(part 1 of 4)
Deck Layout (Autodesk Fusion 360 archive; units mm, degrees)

design "Deck Layout" references "Pinball Flipper Full bushing"
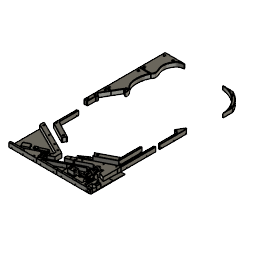
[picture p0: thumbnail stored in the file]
parameter "d345" = 2.4
sketch "Deck" plane through (0, 0, 0) normal (0, 0, 1) x axis (1, 0, 0)
  line L1 (500, 0) -> (0, 0)
  line L2 (500, 900) -> (500, 0)
  line L3 (0, 900) -> (500, 900)
  line L4 (0, 0) -> (0, 900)
  line L5 (250, 900) -> (250, 0)
  line L6 (265, 900) -> (265, 0)
  line L7 (235, 900) -> (235, 0)
  line L8 (475, 900) -> (475, 0)
  line L9 (25, 900) -> (25, 0)
  line L10 (500, 205) -> (0, 205)
  line L11 (500, 175) -> (0, 175)
  line L12 (175, 0) -> (175, 900)
  line L13 (325, 900) -> (325, 0)
  line L14 (187.7232, 167.6543) -> (175, 175)
  line L15 (189.6915, 175) -> (175, 175)
  line L16 (317.6007, 170.728) -> (325, 175)
  line L17 (333.544, 175) -> (325, 175)
  line L18 (317, 900) -> (317, 0)
  line L19 (183, 0) -> (183, 900)
  line L20 (500, 100) -> (0, 100)
  line L21 (500, 750) -> (500, 900)
  line L22 (500, 818.9103) -> (500, 750)
  line L23 (418.7386, 900) -> (350, 900)
  line L24 (0, 810) -> (500, 810)
  line L25 (0, 760) -> (500, 760)
  arc A1 centre (350, 750) radius 150 clockwise from (350, 900) to (500, 750)
  arc A2 centre (350, 750) radius 165 clockwise from (418.7386, 900) to (500, 818.7386)
  circle C1 centre (416.5624, 892.7435) radius 5
  circle C2 centre (416.5624, 892.7435) radius 2
  circle C3 centre (416.5624, 892.7435) radius 2
  circle C4 centre (416.5624, 892.7435) radius 5
  circle C5 centre (492.7435, 816.5624) radius 5
  circle C6 centre (492.7435, 816.5624) radius 2
  point P1 (0, 0)
  point P2 (0, 0)
  point P6 (0, 0)
  point P7 (250, 0)
  point P8 (250, 900)
  point P25 (175, 175)
  point P28 (325, 175)
  point P40 (350, 900)
  point P38 (350, 750)
  point P41 (350, 750)
  point P42 (500, 818.9103)
  point P43 (500, 818.7386)
  point P44 (418.7386, 900)
  coincident P1 P2
  horizontal L1
  perpendicular L1 L2
  perpendicular L2 L3
  coincident P1 P6
  perpendicular L1 L4
  midpoint L1 P7
  midpoint L3 P8
  horizontal L10
  horizontal L11
  horizontal L15
  coincident L11 P25
  coincident L12 P25
  horizontal L17
  coincident L11 P28
  coincident L13 P28
  horizontal L20
  perpendicular L3 L21
  coincident L3 P40
  coincident P38 P41
  coincident L21 P42
  coincident L2 P43
  coincident L3 P44
  tangent A1 L23
  concentric C1 C2
  concentric C3 C4
  concentric C5 C6
  dimension "d4" angle L14 L15 = 30
  dimension "d5" angle L16 L17 = 150
extrude "Extrude1" new body sketch "Deck" profile of L1 L2 L3 L4 L5 L6 L7 L8 L9 L10 L11 L12 L13 against normal blind 9
external_derived "ExternalDerived1"
move "Move1"
move "Move2"
move "Move3"
sketch "SCRATCH Sketch2" plane through (0, 0, 0) normal (0, 0, 1) x axis (1, 0, 0)
  line L1 (170.3253, 163.25) -> (183.8331, 184.2525)
  line L2 (165.6625, 180.1712) -> (177.0792, 173.7512)
  arc A1 centre (176.5753, 174.0753) radius 12.5 clockwise from (170.3253, 163.25) to (183.6642, 184.3709)
  point P2 (183.8331, 184.2525)
  point P4 (183.8331, 184.2525)
  point P3 (170.3253, 163.25)
  point P5 (170.3253, 163.25)
  point P9 (177.0792, 173.7512)
  point P10 (165.6625, 180.1712)
  coincident P2 P4
  coincident P3 P5
  midpoint L1 P9
  coincident A1 P10
move "Move4"
copy_paste_bodies "CopyPasteBodies1"
move "Move5"
move "Move6"
sketch "SCRATCH Sketch3" plane through (0, 0, 25.4) normal (0, 0, 1) x axis (-1, 0, 0)
  line L1 (-298.3283, -100.9362) -> (-297.8341, -101.7922)
  line L2 (-297.584, -100.5065) -> (-298.3283, -100.9362)
  line L3 (-297.0898, -101.3625) -> (-297.584, -100.5065)
  line L4 (-297.8341, -101.7922) -> (-297.0898, -101.3625)
  line L5 (-303.1949, -96.8044) -> (-299.6949, -102.8666)
  line L6 (-302.4506, -96.3746) -> (-303.1949, -96.8044)
  line L7 (-298.9506, -102.4368) -> (-302.4506, -96.3746)
  line L8 (-299.6949, -102.8666) -> (-298.9506, -102.4368)
  line L9 (-305.0971, -97.9026) -> (-302.5616, -102.2942)
  line L10 (-304.3528, -97.4729) -> (-305.0971, -97.9026)
  line L11 (-301.8173, -101.8644) -> (-304.3528, -97.4729)
  line L12 (-302.5616, -102.2942) -> (-301.8173, -101.8644)
  line L13 (-336.6609, -113.8819) -> (-335.4266, -116.0198)
  line L14 (-335.9166, -113.4522) -> (-336.6609, -113.8819)
  line L15 (-332.4094, -119.5268) -> (-335.9166, -113.4522)
  line L16 (-333.0876, -119.9183) -> (-332.4094, -119.5268)
  line L17 (-333.417, -119.3477) -> (-333.0876, -119.9183)
  curve K1 (-333.6687, -120.1628) -> (-333.417, -119.3477)
  curve K2 (-334.3039, -120.7529) -> (-333.6687, -120.1628)
  curve K3 (-335.4635, -121.0364) -> (-334.3039, -120.7529)
  curve K4 (-336.5842, -120.5946) -> (-335.4635, -121.0364)
  curve K5 (-337.4707, -119.5653) -> (-336.5842, -120.5946)
  curve K6 (-337.9295, -118.212) -> (-337.4707, -119.5653)
  curve K7 (-337.704, -116.9791) -> (-337.9295, -118.212)
  curve K8 (-336.9002, -116.1318) -> (-337.704, -116.9791)
  curve K9 (-336.1417, -115.9034) -> (-336.9002, -116.1318)
  curve K10 (-335.4266, -116.0198) -> (-336.1417, -115.9034)
  line L18 (-315.9189, -104.1506) -> (-314.5342, -106.549)
  line L19 (-315.1746, -103.7208) -> (-315.9189, -104.1506)
  line L20 (-312.6391, -108.1124) -> (-315.1746, -103.7208)
  line L21 (-313.309, -108.4992) -> (-312.6391, -108.1124)
  line L22 (-313.6695, -107.8747) -> (-313.309, -108.4992)
  curve K11 (-314.6494, -109.4054) -> (-313.6695, -107.8747)
  curve K12 (-315.4616, -109.6841) -> (-314.6494, -109.4054)
  curve K13 (-316.176, -109.5975) -> (-315.4616, -109.6841)
  curve K14 (-316.7251, -109.1812) -> (-316.176, -109.5975)
  curve K15 (-317.1842, -108.4815) -> (-316.7251, -109.1812)
  line L23 (-318.7432, -105.7812) -> (-317.1842, -108.4815)
  line L24 (-317.9989, -105.3514) -> (-318.7432, -105.7812)
  line L25 (-316.4566, -108.0228) -> (-317.9989, -105.3514)
  curve K16 (-315.977, -108.6529) -> (-316.4566, -108.0228)
  curve K17 (-315.4612, -108.8348) -> (-315.977, -108.6529)
  curve K18 (-314.8647, -108.6695) -> (-315.4612, -108.8348)
  curve K19 (-314.2181, -107.8938) -> (-314.8647, -108.6695)
  curve K20 (-314.5342, -106.549) -> (-314.2181, -107.8938)
  line L26 (-329.0977, -111.7594) -> (-327.7106, -114.1619)
  line L27 (-328.3534, -111.3296) -> (-329.0977, -111.7594)
  line L28 (-324.8534, -117.3918) -> (-328.3534, -111.3296)
  line L29 (-325.5977, -117.8215) -> (-324.8534, -117.3918)
  line L30 (-326.8535, -115.6464) -> (-325.5977, -117.8215)
  curve K21 (-327.8199, -117.0094) -> (-326.8535, -115.6464)
  curve K22 (-328.7787, -117.3065) -> (-327.8199, -117.0094)
  curve K23 (-329.6003, -117.0724) -> (-328.7787, -117.3065)
  curve K24 (-330.3236, -116.1777) -> (-329.6003, -117.0724)
  line L31 (-331.9303, -113.3948) -> (-330.3236, -116.1777)
  line L32 (-331.186, -112.965) -> (-331.9303, -113.3948)
  line L33 (-329.5792, -115.748) -> (-331.186, -112.965)
  curve K25 (-328.8682, -116.4209) -> (-329.5792, -115.748)
  curve K26 (-328.037, -116.2801) -> (-328.8682, -116.4209)
  curve K27 (-327.5137, -115.7492) -> (-328.037, -116.2801)
  curve K28 (-327.3667, -115.044) -> (-327.5137, -115.7492)
  curve K29 (-327.7106, -114.1619) -> (-327.3667, -115.044)
  line L34 (-333.8118, -114.4811) -> (-331.2763, -118.8726)
  line L35 (-333.0675, -114.0513) -> (-333.8118, -114.4811)
  line L36 (-330.532, -118.4429) -> (-333.0675, -114.0513)
  line L37 (-331.2763, -118.8726) -> (-330.532, -118.4429)
  line L38 (-330.806, -119.6872) -> (-330.3118, -120.5432)
  line L39 (-330.0617, -119.2575) -> (-330.806, -119.6872)
  line L40 (-329.5675, -120.1135) -> (-330.0617, -119.2575)
  line L41 (-330.3118, -120.5432) -> (-329.5675, -120.1135)
  curve K30 (-325.4642, -110.9573) -> (-324.5473, -109.9096)
  curve K31 (-325.4308, -112.4762) -> (-325.4642, -110.9573)
  line L42 (-326.35, -112.7368) -> (-325.4308, -112.4762)
  curve K32 (-326.3126, -110.7055) -> (-326.35, -112.7368)
  curve K33 (-325.0098, -109.2614) -> (-326.3126, -110.7055)
  curve K34 (-323.1853, -108.7401) -> (-325.0098, -109.2614)
  curve K35 (-321.5835, -109.3563) -> (-323.1853, -108.7401)
  curve K36 (-320.3247, -110.7964) -> (-321.5835, -109.3563)
  curve K37 (-319.7328, -112.6573) -> (-320.3247, -110.7964)
  curve K38 (-320.1441, -114.3228) -> (-319.7328, -112.6573)
  curve K39 (-321.4028, -115.5375) -> (-320.1441, -114.3228)
  curve K40 (-323.2003, -115.9577) -> (-321.4028, -115.5375)
  curve K41 (-324.8166, -115.1541) -> (-323.2003, -115.9577)
  line L43 (-324.1342, -114.512) -> (-324.8166, -115.1541)
  curve K42 (-322.9659, -115.1221) -> (-324.1342, -114.512)
  curve K43 (-321.7826, -114.8415) -> (-322.9659, -115.1221)
  curve K44 (-320.8078, -113.8321) -> (-321.7826, -114.8415)
  curve K45 (-320.6675, -112.5519) -> (-320.8078, -113.8321)
  curve K46 (-321.1494, -111.278) -> (-320.6675, -112.5519)
  curve K47 (-322.1542, -110.058) -> (-321.1494, -111.278)
  curve K48 (-323.3529, -109.6005) -> (-322.1542, -110.058)
  curve K49 (-324.5473, -109.9096) -> (-323.3529, -109.6005)
  curve K50 (-310.472, -101.6619) -> (-312.3041, -101.9313)
  curve K51 (-308.9198, -103.0373) -> (-310.472, -101.6619)
  curve K52 (-308.5546, -105.236) -> (-308.9198, -103.0373)
  curve K53 (-309.6541, -106.5213) -> (-308.5546, -105.236)
  curve K54 (-311.4771, -106.7826) -> (-309.6541, -106.5213)
  curve K55 (-312.9985, -105.4749) -> (-311.4771, -106.7826)
  curve K56 (-313.5141, -103.9945) -> (-312.9985, -105.4749)
  curve K57 (-313.2096, -102.8124) -> (-313.5141, -103.9945)
  curve K58 (-312.3041, -101.9313) -> (-313.2096, -102.8124)
  curve K59 (-308.2724, -100.7779) -> (-307.6957, -100.0866)
  curve K60 (-308.1671, -101.8199) -> (-308.2724, -100.7779)
  line L44 (-308.954, -102.1473) -> (-308.1671, -101.8199)
  curve K61 (-309.0239, -100.6081) -> (-308.954, -102.1473)
  curve K62 (-308.0573, -99.4794) -> (-309.0239, -100.6081)
  curve K63 (-306.2677, -99.2318) -> (-308.0573, -99.4794)
  curve K64 (-304.7445, -100.6047) -> (-306.2677, -99.2318)
  curve K65 (-304.2616, -101.9855) -> (-304.7445, -100.6047)
  curve K66 (-304.5171, -103.1999) -> (-304.2616, -101.9855)
  curve K67 (-305.4114, -104.0718) -> (-304.5171, -103.1999)
  curve K68 (-306.7905, -104.3856) -> (-305.4114, -104.0718)
  curve K69 (-307.9669, -103.6947) -> (-306.7905, -104.3856)
  line L45 (-307.3077, -103.1652) -> (-307.9669, -103.6947)
  curve K70 (-306.5573, -103.6197) -> (-307.3077, -103.1652)
  curve K71 (-305.7937, -103.4765) -> (-306.5573, -103.6197)
  curve K72 (-305.1126, -102.5457) -> (-305.7937, -103.4765)
  curve K73 (-305.4976, -101.0671) -> (-305.1126, -102.5457)
  curve K74 (-306.5792, -99.9768) -> (-305.4976, -101.0671)
  curve K75 (-307.6957, -100.0866) -> (-306.5792, -99.9768)
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  point P165 (-326.7759, -128.0741)
  point P171 (-326.7759, -128.0741)
  point P169 (-338.2107, -105.8748)
  point P172 (-338.2107, -105.8748)
  point P173 (-332.5441, -116.6768)
  coincident P165 P171
  coincident P169 P172
  midpoint L34 P173
move "Move7"
move "Move8"
move "Move9"
sketch "Bottom Runways" plane through (0, 0, 0) normal (0, 0, 1) x axis (1, 0, 0)
  line L1 (35, 200) -> (235, 100)
  line L2 (382.2216, 133.6108) -> (309.7214, 97.3607)
  line L3 (265, 100) -> (265, 84.3827)
  line L4 (235, 75) -> (235, 100)
  line L5 (30, 177.5) -> (215, 85)
  line L6 (187.1443, 36.0721) -> (235, 60)
  line L7 (235, 60) -> (235, 75)
  line L8 (215, 70) -> (215, 85)
  line L9 (205, 45) -> (201.3653, 45.918)
  line L10 (197.2105, 61.1053) -> (215, 70)
  line L11 (95, 10) -> (170.0223, 47.5111)
  line L12 (475.0759, 10) -> (475.0759, 180)
  line L13 (500, 35) -> (496.5, 55)
  line L14 (500, 55) -> (500, 55)
  line L15 (500, 35) -> (500, 55)
  line L16 (475.0759, 35.4337) -> (478.5, 55)
  line L17 (500, 60) -> (500, 55)
  line L18 (465, 101) -> (475.0759, 96.9696)
  line L19 (465, 20) -> (465, 70)
  line L20 (436.9865, 55.459) -> (436.9865, 85.2054)
  line L21 (442.002, 24.3778) -> (442.002, 10)
  line L22 (437.4865, 56.1294) -> (437.4865, 75.0054)
  line L23 (442.489, 73.0044) -> (464.5, 64.2)
  line L24 (441.9865, 73.2054) -> (442.489, 73.0044)
  line L25 (464.5, 23) -> (455.75, 23)
  line L26 (455.75, 23) -> (455.75, 44.291)
  line L27 (464.5, 23) -> (464.5, 64.2)
  line L28 (437.4865, 85.0054) -> (437.4865, 75.0054)
  line L29 (441.9885, 83.2046) -> (441.9908, 73.2037)
  line L30 (382.2216, 106.6108) -> (387.2417, 104.6487)
  line L31 (437.4865, 121.6401) -> (437.4865, 85.0054)
  line L32 (441.9885, 121.6401) -> (441.9885, 83.2046)
  line L33 (437.4865, 121.6401) -> (441.9885, 121.6401)
  line L34 (436.9865, 133.2054) -> (436.9865, 112.2054)
  line L35 (436.9865, 133.2054) -> (441.4885, 133.2054)
  line L36 (442.4885, 133.2054) -> (441.4885, 133.2054)
  line L37 (442.4885, 110.0046) -> (442.4885, 133.2054)
  line L38 (442.4885, 110.0046) -> (465, 101)
  line L39 (438.1128, 101.7549) -> (441.9885, 100.2046)
  line L40 (437.4865, 102.0054) -> (438.1128, 101.7549)
  line L41 (437.4865, 75.0054) -> (441.9865, 73.2054)
  line L42 (465, 10) -> (465, 20)
  line L43 (475.0759, 180) -> (475.0152, 200)
  line L44 (265, 84.3827) -> (265, 86.0924)
  line L45 (265, 48) -> (265, 84.5)
  line L46 (265, 48) -> (265.011, 48.0055)
  line L47 (189, 10) -> (264.7, 47.85)
  line L48 (0.189, -124.2988) -> (0.189, 200)
  line L49 (500, 0) -> (500, 10)
  line L50 (189, 0) -> (264.7, 0)
  line L51 (189, 10) -> (189, 0)
  line L52 (188.3292, 10) -> (197.8101, 14.7405)
  line L53 (188.3292, 10) -> (30, 10)
  line L54 (188.3292, 0) -> (188.3292, 10)
  line L55 (30, 0) -> (188.3292, 0)
  line L56 (305, 26.7) -> (310.3, 26.7)
  line L57 (310.3, 32.3) -> (305, 32.3)
  line L58 (304.7, 32) -> (304.7, 47.85)
  line L59 (305, 0) -> (305, 10)
  line L60 (304.7, 0) -> (304.7, 10)
  line L61 (310, 27) -> (310, 32)
  line L62 (310, 32) -> (304.7, 32)
  line L63 (305, 10) -> (305, 26.7)
  line L64 (304.7, 27) -> (310, 27)
  line L65 (304.7, 10) -> (304.7, 27)
  line L66 (305, 32.3) -> (305, 48)
  line L67 (310.3, 26.7) -> (310.3, 32.3)
  line L68 (304.7076, 119.8538) -> (265, 100)
  line L69 (465, 200) -> (305.0076, 120.0038)
  line L70 (304.705, 95.4133) -> (269.0857, 81.586)
  line L71 (309.7214, 97.3607) -> (305.005, 95.5298)
  line L72 (304.7021, 67.8511) -> (265.011, 48.0055)
  line L73 (382.2216, 106.6108) -> (305.0021, 68.0011)
  line L74 (310.3, 112.3) -> (305, 112.3)
  line L75 (310, 112) -> (304.7, 112)
  line L76 (310, 107) -> (310, 112)
  line L77 (310.3, 106.7) -> (310.3, 112.3)
  line L78 (304.7, 107) -> (310, 107)
  line L79 (305, 106.7) -> (310.3, 106.7)
  line L80 (305.0062, 106.7) -> (305, 48)
  line L81 (305.0076, 120.0038) -> (305.0068, 112.3)
  line L82 (265, 48) -> (264.7, 47.85)
  line L83 (265, 0) -> (264.7, 0)
  line L84 (304.7, 10) -> (189, 10)
  line L85 (500, 10) -> (305, 10)
  line L86 (305, 0) -> (500, 0)
  line L87 (265, 0) -> (304.7, 0)
  line L88 (382.2216, 96.6108) -> (305.0021, 58.0011)
  line L89 (382.2216, 96.6108) -> (387.2417, 94.6487)
  line L90 (305.0011, 58.0005) -> (305.0021, 58.0011)
  line L91 (305.0011, 58.0005) -> (305.0021, 58.0011)
  line L92 (209, 10) -> (304.7011, 57.8505)
  line L93 (304.7062, 107) -> (304.7, 47.85)
  line L94 (304.7076, 119.8538) -> (304.7067, 112)
  line L95 (455.25, 30) -> (455.25, 23)
  line L96 (455.25, 10) -> (455.25, 23)
  line L97 (426.9865, 59.7353) -> (436.9865, 59.7353)
  line L98 (452.1681, 30) -> (455.25, 30)
  line L99 (441.9908, 56.2022) -> (441.9908, 73.2037)
  line L100 (465, 200) -> (0.189, 200)
  line L101 (30, 200) -> (35, 200)
  line L102 (30, 0) -> (30, 200)
  line L103 (470.038, 72.2189) -> (475.0759, 72.2189)
  line L104 (465, 70) -> (470.038, 72.2189)
  line L105 (414.4865, 128) -> (414.4865, 95.0841)
  line L106 (414.4865, 73) -> (414.4865, 95.0841)
  line L107 (409.9865, 128) -> (409.9865, 95.0841)
  line L108 (409.9865, 73) -> (409.9865, 95.0841)
  line L109 (414.9865, 128) -> (414.9865, 120.8043)
  line L110 (414.4865, 141.8043) -> (409.9865, 141.8043)
  line L111 (414.9865, 141.8043) -> (414.4865, 141.8043)
  line L112 (414.9865, 141.8043) -> (414.9865, 128.0189)
  line L113 (409.4865, 141.8043) -> (409.4865, 128)
  line L114 (409.4865, 141.8043) -> (409.9865, 141.8043)
  line L115 (414.9865, 120.8043) -> (436.9865, 112.2054)
  line L116 (382.2216, 133.6108) -> (409.4865, 122.9541)
  line L117 (414.4865, 73) -> (409.9865, 73)
  line L118 (409.4865, 61) -> (409.4865, 95.0841)
  line L119 (414.9865, 61) -> (409.4865, 61)
  line L120 (414.9865, 61) -> (414.9865, 93.8043)
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  point P16 (189, 10)
  point P17 (95, 10)
  point P20 (170.0223, 47.5111)
  point P23 (205, 45)
  point P28 (197.2105, 61.1053)
  point P26 (185.8525, 49.8361)
  point P27 (185.8525, 49.8361)
  point P33 (475.0759, 10)
  point P38 (475.0759, 35.4337)
  point P41 (475.0759, 59.9858)
  point P54 (441.9865, 73.2054)
  point P46 (440, 40)
  point P59 (440, 40)
  point P76 (441.9908, 73.2037)
  point P88 (437.4865, 102.0054)
  point P89 (441.9885, 100.2046)
  point P53 (442.002, 10)
  point P91 (465, 10)
  point P92 (475.0759, 72.2189)
  point P93 (475.0759, 96.9696)
  point P94 (265, 86.0924)
  point P96 (264.7, 47.85)
  point P97 (265, 84.5)
  point P30 (0.189, -124.2988)
  point P98 (0.189, -124.2988)
  point P32 (500, 0)
  point P99 (500, 0)
  point P108 (304.7, 27)
  point P120 (305.0076, 120.0038)
  point P122 (304.705, 95.4133)
  point P123 (305.005, 95.5298)
  point P124 (304.7021, 67.8511)
  point P125 (305.0021, 68.0011)
  point P134 (305.0068, 112.3)
  point P135 (305.0062, 106.7)
  point P139 (305.0011, 58.0005)
  point P140 (209, 10)
  point P141 (304.7011, 57.8505)
  point P142 (304.7062, 107)
  point P143 (304.7067, 112)
  point P144 (440, 40)
  point P146 (455.25, 10)
  point P147 (436.9865, 59.7353)
  point P202 (35, 200)
  point P204 (475.0152, 200)
  point P207 (30, 177.5)
  point P208 (30, 10)
  point P236 (409.9865, 95.7586)
  point P237 (414.4865, 93.9998)
  point P238 (409.9865, 122.7586)
  point P239 (414.4865, 120.9998)
  point P22 (185.8525, 49.8361)
  point P252 (185.8525, 49.8361)
  point P21 (185.8525, 49.8361)
  point P253 (185.8525, 49.8361)
  parallel L2 L6
  parallel L4 L7
  vertical L8
  coincident P16 L53
  coincident P17 L53
  coincident P20 L10
  coincident L6 P23
  coincident P28 L10
  coincident P26 P27
  collinear L10 L11
  coincident P33 L53
  perpendicular L12 L53
  coincident L12 P38
  coincident L12 P41
  perpendicular L19 L53
  vertical L20
  vertical L27
  coincident P54 L23
  vertical L22
  coincident P46 P59
  perpendicular L25 L27
  parallel L22 L28
  coincident L24 P76
  parallel L18 L38
  parallel L28 L31
  perpendicular L31 L33
  parallel L28 L34
  parallel L35 L36
  perpendicular L36 L37
  parallel L39 L40
  coincident L31 P88
  coincident L32 P89
  parallel L24 L41
  coincident P53 L53
  perpendicular L21 L53
  coincident P91 L53
  perpendicular L42 L53
  coincident L12 P92
  coincident L12 P93
  coincident L3 P94
  perpendicular L44 L53
  coincident P96 L46
  collinear L46 L47
  coincident L3 P97
  coincident P30 P98
  perpendicular L48 L53
  coincident P32 P99
  perpendicular L49 L53
  perpendicular L49 L86
  collinear L53 L84
  perpendicular L50 L54
  perpendicular L62 L66
  perpendicular L61 L62
  coincident P108 L58
  perpendicular L58 L64
  collinear L58 L65
  collinear L63 L66
  perpendicular L57 L66
  perpendicular L57 L67
  perpendicular L56 L63
  coincident P120 L68
  parallel L80 L93
  collinear L68 L69
  coincident P122 L93
  coincident P123 L80
  collinear L70 L71
  coincident P124 L93
  coincident P125 L80
  collinear L72 L73
  perpendicular L75 L76
  perpendicular L74 L77
  coincident L74 P134
  collinear L80 L81
  coincident L79 P135
  parallel L72 L82
  collinear L84 L85
  collinear L86 L87
  parallel L88 L90
  coincident L80 P139
  parallel L88 L91
  coincident L84 P140
  coincident P141 L93
  collinear L91 L92
  coincident L78 P142
  coincident L75 P143
  collinear L93 L94
  coincident P59 P144
  coincident L85 P146
  perpendicular L85 L96
  coincident L20 P147
  perpendicular L95 L98
  vertical L99
  coincident P202 L100
  collinear L100 L101
  coincident L100 P204
  perpendicular L55 L102
  coincident L102 P207
  coincident L102 P208
  perpendicular L12 L103
  parallel L110 L111
  perpendicular L111 L112
  perpendicular L113 L114
  collinear L115 L116
  perpendicular L106 L117
  parallel L108 L118
  perpendicular L118 L119
  perpendicular L119 L120
  coincident L107 P236
  coincident L106 P237
  coincident L107 P238
  coincident L105 P239
  coincident P22 P252
  coincident P21 P253
  dimension "d8" radius = 3
  dimension "d40" radius = 16
  dimension "d225" diameter = 7.6
  dimension "d290" diameter = 8
  dimension "d293" diameter = 8
  dimension "d363" radius = 2
  dimension "d364" radius = 1.5
  dimension "d443" diameter = 8
  dimension "d444" diameter = 8
  dimension "d445" diameter = 3.8
  dimension "d446" diameter = 3.8
  dimension "d463" diameter = 8
  dimension "d464" diameter = 8
  dimension "d465" diameter = 3.8
  dimension "d466" diameter = 3.8
  dimension "d494" diameter = 18
  dimension "d495" diameter = 4.5
  dimension "d496" diameter = 24
  dimension "d497" diameter = 8
  dimension "d498" diameter = 8
  dimension "d499" diameter = 4.5
  dimension "d500" diameter = 4.5
  dimension "d510" diameter = 100
  dimension "d514" diameter = 8
  dimension "d515" diameter = 4.5
  dimension "d516" diameter = 8
  dimension "d517" diameter = 4.5
  dimension "d518" diameter = 8
  dimension "d519" diameter = 4.5
  dimension "d524" diameter = 8
  dimension "d525" diameter = 4.5
sketch "Reload Plunger" plane through (0, 0, 0) normal (0, 0, 1) x axis (1, 0, 0)
  line L1 (107.246, 52.5518) -> (74.0474, 36.2161)
  line L2 (111.2277, 44.4598) -> (130.0702, 53.7314)
  line L3 (113.0223, 45.3428) -> (130.0702, 53.7314)
  line L4 (109.0487, 53.4181) -> (84.7472, 41.481)
  line L5 (111.2277, 44.4598) -> (130.0702, 53.7314)
  line L6 (74.0474, 36.2161) -> (85.5333, 12.8737)
  line L7 (130.9104, 45.2288) -> (127.3784, 52.4069)
  line L8 (116.5543, 38.1647) -> (113.0223, 45.3428)
  line L9 (130.0702, 53.7314) -> (133.6022, 46.5533)
  line L10 (128.2187, 43.9043) -> (124.6866, 51.0824)
  line L11 (116.5543, 38.1647) -> (133.6022, 46.5533)
  line L12 (130.0702, 53.7314) -> (133.6022, 46.5533)
  line L13 (118.7318, 29.2095) -> (107.246, 52.5518)
  line L14 (130.9104, 45.2288) -> (127.3784, 52.4069)
  line L15 (96.2312, 18.1378) -> (120.5273, 30.0906)
  line L16 (107.246, 52.5518) -> (74.0474, 36.2161)
  line L17 (84.7472, 41.481) -> (96.2312, 18.1378)
  line L18 (85.5333, 12.8737) -> (118.7318, 29.2095)
  line L19 (133.6022, 46.5533) -> (114.7598, 37.2817)
  line L20 (128.2187, 43.9043) -> (124.6866, 51.0824)
  line L21 (114.7598, 37.2817) -> (111.2277, 44.4598)
  line L22 (94.4613, 19.4702) -> (117.83, 30.8678)
  line L23 (108.1858, 50.6413) -> (74.9304, 34.4215)
  line L24 (108.1858, 50.6413) -> (84.8172, 39.2436)
  line L25 (108.1858, 50.6413) -> (74.9304, 34.4215)
  line L26 (108.1858, 50.6413) -> (74.9304, 34.4215)
  line L27 (85.7923, 24.6991) -> (91.2583, 27.3626)
  line L28 (108.1858, 50.6413) -> (117.83, 30.8678)
  line L29 (117.83, 30.8678) -> (84.5746, 14.6481)
  line L30 (117.83, 30.8678) -> (84.5746, 14.6481)
  line L31 (117.83, 30.8678) -> (84.5746, 14.6481)
  line L32 (110.4742, 33.3995) -> (105.2009, 30.8342)
  line L33 (105.6521, 43.2862) -> (100.3841, 40.7101)
  line L34 (88.992, 31.8227) -> (83.6843, 29.2374)
  line L35 (74.9304, 34.4215) -> (84.5746, 14.6481)
  line L36 (109.1591, 36.0958) -> (103.891, 33.5197)
  line L37 (108.1858, 50.6413) -> (117.83, 30.8678)
  line L38 (108.1858, 50.6413) -> (117.83, 30.8678)
  line L39 (74.9304, 34.4215) -> (84.5746, 14.6481)
  line L40 (106.9672, 40.5898) -> (101.6939, 38.0245)
  line L41 (92.4997, 24.6327) -> (87.1069, 22.0025)
  line L42 (74.9304, 34.4215) -> (84.5746, 14.6481)
  line L43 (87.6776, 34.5194) -> (82.2849, 31.8892)
  line L44 (85.7923, 24.6991) -> (91.1137, 27.2922)
  line L45 (84.8172, 39.2436) -> (94.4613, 19.4702)
  line L46 (92.4997, 24.6327) -> (87.1069, 22.0025)
  line L47 (117.83, 30.8678) -> (108.1858, 50.6413)
  line L48 (74.9304, 34.4215) -> (74.0474, 36.2161)
  arc A1 centre (104.4253, 32.1181) radius 1.5 clockwise from (105.2015, 30.8345) to (103.8917, 33.52)
  arc A2 centre (100.9183, 39.3084) radius 1.5 clockwise from (101.6945, 38.0249) to (100.3847, 40.7103)
  arc A3 centre (109.818, 34.7483) radius 1.5 clockwise from (109.1591, 36.0958) to (110.4742, 33.3995)
  arc A4 centre (82.9424, 30.541) radius 1.5 clockwise from (83.6843, 29.2374) to (82.2849, 31.8892)
  circle C1 centre (103.6147, 40.6236) radius 1.5
  arc A5 centre (91.8421, 25.9809) radius 1.5 clockwise from (91.2583, 27.3626) to (92.4997, 24.6327)
  circle C2 centre (103.6147, 40.6236) radius 1.5
  arc A6 centre (106.3111, 41.9387) radius 1.5 clockwise from (105.6521, 43.2862) to (106.9672, 40.5898)
  circle C3 centre (111.1442, 33.1699) radius 1.8
  circle C4 centre (107.1216, 33.4332) radius 1.5
  arc A7 centre (100.9183, 39.3084) radius 1.5 clockwise from (101.6945, 38.0249) to (100.3847, 40.7103)
  arc A8 centre (86.4494, 23.3507) radius 1.5 clockwise from (87.1069, 22.0025) to (85.7923, 24.6991)
  arc A9 centre (82.9424, 30.541) radius 1.5 clockwise from (83.6845, 29.2374) to (82.2849, 31.8892)
  arc A10 centre (91.8421, 25.9809) radius 1.5 clockwise from (91.1137, 27.2922) to (92.4997, 24.6327)
  arc A11 centre (86.4494, 23.3507) radius 1.5 clockwise from (87.1069, 22.0025) to (85.7923, 24.6991)
  arc A12 centre (86.4494, 23.3507) radius 1.5 clockwise from (87.1069, 22.0025) to (85.7923, 24.6991)
  circle C5 centre (107.1216, 33.4332) radius 1.5
  circle C6 centre (89.1458, 24.6658) radius 1.5
  arc A13 centre (104.4253, 32.1181) radius 1.5 clockwise from (105.2015, 30.8345) to (103.8917, 33.52)
  circle C7 centre (91.9524, 37.1607) radius 1.8
  arc A14 centre (88.3352, 33.1712) radius 1.5 clockwise from (87.6776, 34.5194) to (88.992, 31.8227)
  circle C8 centre (89.1458, 24.6658) radius 1.5
  circle C9 centre (89.1458, 24.6658) radius 1.5
  arc A15 centre (82.9424, 30.541) radius 1.5 clockwise from (83.6845, 29.2374) to (82.2849, 31.8892)
  circle C10 centre (85.6388, 31.8561) radius 1.5
  circle C11 centre (107.1216, 33.4332) radius 1.5
  arc A16 centre (104.4253, 32.1181) radius 1.5 clockwise from (105.2009, 30.8342) to (103.891, 33.5197)
  circle C12 centre (103.6147, 40.6236) radius 1.5
  circle C13 centre (85.6388, 31.8561) radius 1.5
  arc A17 centre (100.9183, 39.3084) radius 1.5 clockwise from (101.6939, 38.0245) to (100.3841, 40.7101)
  circle C14 centre (85.6388, 31.8561) radius 1.5
  circle C15 centre (111.1442, 33.1699) radius 3.25
  circle C16 centre (107.1216, 33.4332) radius 3.25
  circle C17 centre (103.6147, 40.6236) radius 3.25
  circle C18 centre (91.9524, 37.1607) radius 3.25
  circle C19 centre (89.1458, 24.6658) radius 3.25
  circle C20 centre (85.6388, 31.8561) radius 3.25
  point P11 (133.6022, 46.5533)
  point P33 (133.6022, 46.5533)
  point P12 (130.0702, 53.7314)
  point P28 (130.0702, 53.7314)
  point P30 (133.6022, 46.5533)
  point P3 (127.3784, 52.4069)
  point P15 (127.3784, 52.4069)
  point P2 (130.9104, 45.2288)
  point P10 (130.9104, 45.2288)
  point P29 (124.6866, 51.0824)
  point P35 (124.6866, 51.0824)
  point P34 (128.2187, 43.9043)
  point P36 (128.2187, 43.9043)
  point P27 (84.7472, 41.481)
  point P40 (94.4613, 19.4702)
  point P41 (94.4613, 19.4702)
  point P45 (94.4613, 19.4702)
  point P22 (74.0474, 36.2161)
  point P136 (74.9304, 34.4215)
  coincident P11 P33
  coincident P12 P28
  perpendicular L3 L12
  perpendicular L5 L8
  coincident P30 P33
  perpendicular L8 L11
  coincident P3 P15
  coincident P2 P10
  coincident P29 P35
  coincident P34 P36
  coincident P27 L16
  perpendicular L15 L17
  coincident P40 P41
  perpendicular L24 L45
  perpendicular L24 L47
  coincident P41 P45
  perpendicular L22 L45
  perpendicular L1 L48
  concentric C3 C15
  dimension "d9" distance P22 P136 = 2
sketch "Reload Flipper" plane through (0, 0, 0) normal (0, 0, 1) x axis (1, 0, 0)
  line L1 (189.2611, 51.9302) -> (189.2253, 51.9883)
  line L2 (182.2905, 34.7509) -> (182.74, 19.3347)
  line L3 (184.5475, 75.9042) -> (188.377, 65.1291)
  line L4 (190.2871, 34.984) -> (190.8175, 16.7929)
  line L5 (193.9662, 36.6294) -> (185.8525, 49.8361)
  line L6 (190.2939, 34.7513) -> (190.1715, 34.95)
  line L7 (170.4136, 70.881) -> (174.243, 60.106)
  circle C1 centre (185.8525, 49.8361) radius 12.5
  arc A1 centre (185.7387, 19.4222) radius 3 clockwise from (185.7275, 16.4222) to (182.74, 19.3347)
  arc A2 centre (185.8525, 49.8361) radius 33.4141 clockwise from (190.8175, 16.7929) to (185.7275, 16.4222)
  circle C2 centre (185.8525, 49.8361) radius 5.375
  arc A3 centre (185.8525, 49.8361) radius 15.5 clockwise from (182.2905, 34.7509) to (174.1149, 59.9593)
  circle C3 centre (177.4806, 73.3926) radius 1.85
  arc A4 centre (177.4806, 73.3926) radius 7.5 clockwise from (170.4136, 70.881) to (184.5475, 75.9042)
  arc A5 centre (185.8525, 49.8361) radius 15.5 clockwise from (197.0999, 39.1709) to (190.1715, 34.95)
  arc A6 centre (185.8525, 49.8361) radius 15.5 clockwise from (174.1149, 59.9593) to (174.243, 60.106)
  arc A7 centre (185.8525, 49.8361) radius 15.5 clockwise from (188.377, 65.1291) to (197.0999, 39.1709)
  point P9 (197.0999, 39.1709)
  point P12 (174.1149, 59.9593)
  point P8 (185.8525, 49.8361)
  point P20 (185.8525, 49.8361)
  point P2 (185.8525, 49.8361)
  point P26 (185.8525, 49.8361)
  point P25 (185.8525, 49.8361)
  point P3 (190.2871, 34.984)
  point P23 (190.2939, 34.7513)
  point P31 (193.9662, 36.6294)
  point P22 (185.8525, 49.8361)
  point P27 (185.8525, 49.8361)
  concentric C2 A7
  coincident P9 L1
  coincident P12 A7
  concentric A3 A7
  concentric C3 A4
  coincident P8 P20
  concentric C1 C2
  coincident P2 P26
  coincident P2 P25
  coincident P3 A5
  coincident P23 L4
  coincident P31 A5
  tangent A1 L2
  tangent A1 A2
  coincident P22 P27
  dimension "d365" diameter C2 = 10.75
  dimension "d366" diameter A7 = 31
  dimension "d367" diameter C3 = 3.7
  dimension "d368" diameter A4 = 15
  dimension "d369" diameter C1 = 25
  dimension "d370" radius A1 = 3
sketch "reload coupling" plane through (0, 0, 0) normal (0, 0, 1) x axis (1, 0, 0)
  line L1 (182.9196, 67.3244) -> (131.992, 42.4436)
  line L2 (177.176, 81.1418) -> (125.3353, 55.9165)
  line L3 (123.51, 50.5264) -> (126.6606, 44.2444)
  line L4 (134.7248, 43.7787) -> (128.4353, 40.7059)
  line L5 (168.7441, 60.399) -> (165.2756, 67.4985)
  line L6 (162.1861, 73.8478) -> (165.2756, 67.4985)
  line L7 (165.9515, 59.4512) -> (162.5974, 66.1594)
  line L8 (159.4249, 72.5042) -> (162.5974, 66.1594)
  line L9 (166.1158, 59.1149) -> (165.9515, 59.4512)
  line L10 (136.3196, 61.2613) -> (142.8863, 47.766)
  line L11 (145.5841, 49.0787) -> (142.8863, 47.766)
  line L12 (139.0173, 62.5741) -> (145.5841, 49.0787)
  line L13 (124.4038, 50.9748) -> (123.51, 50.5264)
  circle C1 centre (130.184, 49.9541) radius 1.9
  arc A1 centre (130.2361, 46.0376) radius 4 clockwise from (131.992, 42.4436) to (126.6606, 44.2444)
  arc A2 centre (127.0855, 52.3197) radius 4 clockwise from (123.51, 50.5264) to (125.3353, 55.9165)
  circle C2 centre (179.5655, 74.0326) radius 1.9
  arc A3 centre (179.5655, 74.0326) radius 7.5 clockwise from (177.176, 81.1418) to (182.9196, 67.3244)
  point P6 (134.7248, 43.7787)
  point P4 (128.4353, 40.7059)
  point P16 (168.7441, 60.399)
  point P17 (162.1861, 73.8478)
  point P2 (179.5655, 74.0326)
  point P20 (179.5655, 74.0326)
  point P21 (166.1158, 59.1149)
  point P22 (159.4249, 72.5042)
  point P23 (142.8863, 47.766)
  point P24 (136.3196, 61.2613)
  point P26 (139.0173, 62.5741)
  point P12 (123.51, 50.5264)
  point P27 (124.4038, 50.9748)
  coincident L1 P6
  coincident P4 L1
  coincident P4 L3
  tangent L1 A1
  tangent L3 A1
  tangent L2 A2
  tangent L3 A2
  coincident L1 P16
  perpendicular L1 L5
  coincident L2 P17
  perpendicular L2 L6
  coincident P2 P20
  coincident L1 P21
  perpendicular L1 L9
  coincident L2 P22
  coincident L1 P23
  coincident L2 P24
  perpendicular L2 L10
  perpendicular L10 L11
  coincident L2 P26
  perpendicular L2 L12
  perpendicular L3 L13
  dimension "d41" distance P4 P6 = 7
  dimension "d42" diameter C1 = 3.8
  dimension "d43" radius A1 = 4
  dimension "d44" radius A2 = 4
  dimension "d347" distance P12 P27 = 1
sketch "Launch Plunger" plane through (0, 0, 0) normal (0, 0, 1) x axis (1, 0, 0)
  line L1 (500, 0) -> (0, 0)
  line L2 (487.5, -9) -> (487.5, 0)
  line L3 (502.5, -9) -> (487.5, -9)
  line L4 (502.5, -12.5) -> (502.5, -9)
  line L5 (472.5, -12.5) -> (502.5, -12.5)
  line L6 (472.5, -9) -> (472.5, -12.5)
  line L7 (487.5, -9) -> (472.5, -9)
  line L8 (495.5, -12.5) -> (487.5, -12.5)
  line L9 (495.5, -28.5) -> (495.5, -12.5)
  line L10 (487.5, -12.5) -> (479.5, -12.5)
  line L11 (479.5, -28.5) -> (479.5, -12.5)
  line L12 (479.5, -28.5) -> (495.5, -28.5)
  line L13 (487.5, -41.5) -> (487.5, -28.5)
  line L14 (494, 9) -> (494, -9)
  line L15 (481, 9) -> (481, -9)
  line L16 (494, 9) -> (481, 9)
  line L17 (481.5, 53) -> (481.5, 9)
  line L18 (493.5, 53) -> (493.5, 9)
  line L19 (493.5, 53) -> (481.5, 53)
  line L20 (479.125, 72) -> (495.875, 72)
  line L21 (493.5, 53) -> (495.875, 72)
  line L22 (481.5, 53) -> (479.125, 72)
  line L23 (493.5, 27) -> (481.5, 27)
  line L24 (479.125, 46) -> (495.875, 46)
  line L25 (481.5, 27) -> (479.125, 46)
  line L26 (493.5, 27) -> (495.875, 46)
  circle C1 centre (487.5, -41.5) radius 13
  point P4 (487.5, 0)
  point P10 (487.5, -12.5)
  point P11 (495.5, -12.5)
  point P17 (487.5, -28.5)
  point P18 (487.5, -41.5)
  point P19 (487.5, -41.5)
  point P26 (481.5, 9)
  point P27 (481.5, 53)
  point P28 (493.5, 9)
  point P29 (493.5, 53)
  coincident L1 P4
  perpendicular L1 L2
  perpendicular L2 L3
  perpendicular L3 L4
  perpendicular L4 L5
  perpendicular L3 L6
  perpendicular L2 L7
  midpoint L5 P10
  coincident L5 P11
  perpendicular L8 L9
  perpendicular L11 L12
  midpoint L12 P17
  perpendicular L12 L13
  coincident P18 P19
  coincident P17 C1
  perpendicular L14 L16
  perpendicular L18 L19
  dimension "d51" distance P17 P18 = 13
  dimension "d55" distance P26 P27 = 44
  dimension "d56" distance P28 P29 = 44
sketch "Launch_reload_Plunger" plane through (0, 0, 0) normal (0, 0, 1) x axis (1, 0, 0)
  line L1 (332.4666, 60.0013) -> (332.3898, 38.0014)
  line L2 (384.4666, 44.9827) -> (384.4666, 52.9827)
  line L3 (343.4665, 59.9629) -> (343.3898, 37.963)
  line L4 (371.4666, 44.9827) -> (390.4666, 44.9827)
  line L5 (369.4666, 52.9827) -> (390.4666, 52.9827)
  line L6 (344.3915, 62.0013) -> (344.3895, 35.9861)
  line L7 (369.4666, 35.9861) -> (369.4666, 62.0013)
  line L8 (363.9352, 51.3914) -> (358.071, 51.4179)
  line L9 (369.3896, 37.8723) -> (369.4664, 59.8721)
  line L10 (371.4666, 52.9827) -> (390.4666, 52.9827)
  line L11 (369.4666, 52.9827) -> (390.4666, 52.9827)
  line L12 (369.4664, 59.8721) -> (369.3896, 37.8723)
  line L13 (390.4666, 52.9827) -> (390.4666, 44.9827)
  line L14 (363.9178, 46.3914) -> (358.0535, 46.4059)
  line L15 (369.4664, 59.8721) -> (369.3896, 37.8723)
  line L16 (387.4666, 44.9827) -> (387.4666, 52.9827)
  line L17 (387.4666, 44.9827) -> (387.4666, 52.9827)
  line L18 (371.4666, 61.9827) -> (344.3915, 62.0013)
  line L19 (390.4666, 44.9827) -> (369.4666, 44.9827)
  line L20 (384.4666, 44.9827) -> (384.4666, 52.9827)
  line L21 (390.4666, 52.9827) -> (390.4666, 44.9827)
  line L22 (332.4666, 60.0013) -> (332.4666, 62.0013)
  line L23 (363.9073, 43.3914) -> (358.0433, 43.4179)
  line L24 (369.4664, 59.8721) -> (332.4666, 60.0013)
  line L25 (369.3896, 37.8723) -> (332.3898, 38.0014)
  line L26 (343.9473, 54.4612) -> (337.9474, 54.4821)
  line L27 (369.4664, 59.8721) -> (343.4665, 59.9629)
  line L28 (371.4666, 44.9827) -> (371.4666, 52.9827)
  line L29 (344.3895, 35.9861) -> (371.4666, 35.9841)
  line L30 (369.4666, 62.0013) -> (332.4666, 62.0013)
  line L31 (343.9361, 51.4612) -> (338.0323, 51.4848)
  line L32 (369.3896, 37.8723) -> (332.3898, 38.0014)
  line L33 (369.4664, 59.8721) -> (332.4666, 60.0013)
  line L34 (343.909, 43.4612) -> (337.909, 43.4822)
  line L35 (337.92, 46.4822) -> (344.0004, 46.4588)
  line L36 (369.4666, 44.9827) -> (369.4666, 52.9827)
  line L37 (369.4664, 59.8721) -> (332.4666, 60.0013)
  line L38 (369.3896, 37.8723) -> (332.3898, 38.0014)
  line L39 (332.4666, 60.0013) -> (332.3898, 38.0014)
  line L40 (343.3898, 37.963) -> (369.3896, 37.8723)
  line L41 (343.909, 43.4612) -> (337.909, 43.4822)
  line L42 (337.92, 46.4822) -> (343.8396, 46.4594)
  line L43 (363.9457, 54.3914) -> (358.0816, 54.4058)
  line L44 (369.4664, 59.8721) -> (369.3896, 37.8723)
  line L45 (332.4666, 35.9861) -> (369.4666, 35.9861)
  line L46 (369.4666, 62.0013) -> (332.4666, 62.0013)
  line L47 (332.4666, 60.0013) -> (332.3898, 38.0014)
  line L48 (332.4666, 62.0013) -> (332.4666, 35.9861)
  circle C1 centre (360.942, 52.9018) radius 1.5
  arc A1 centre (343.9142, 44.9612) radius 1.5 clockwise from (344.0004, 46.4588) to (343.909, 43.4612)
  circle C2 centre (360.9141, 44.9019) radius 1.5
  arc A2 centre (357.9141, 44.9124) radius 1.5 clockwise from (358.0433, 43.4179) to (358.0535, 46.4059)
  circle C3 centre (360.9141, 44.9019) radius 1.5
  arc A3 centre (363.9141, 44.8914) radius 1.5 clockwise from (363.9178, 46.3914) to (363.9073, 43.3914)
  circle C4 centre (364.4071, 42.8897) radius 1.8
  arc A4 centre (337.9421, 52.9821) radius 1.5 clockwise from (338.0323, 51.4848) to (337.9474, 54.4821)
  arc A5 centre (337.9142, 44.9822) radius 1.5 clockwise from (337.909, 43.4822) to (337.92, 46.4822)
  arc A6 centre (337.9142, 44.9822) radius 1.5 clockwise from (337.909, 43.4822) to (337.92, 46.4822)
  circle C5 centre (340.9142, 44.9717) radius 1.5
  circle C6 centre (340.9421, 52.9717) radius 1.5
  circle C7 centre (340.9142, 44.9717) radius 1.5
  arc A7 centre (337.9421, 52.9821) radius 1.5 clockwise from (338.0324, 51.4848) to (337.9474, 54.4821)
  arc A8 centre (357.9141, 44.9124) radius 1.5 clockwise from (358.0439, 43.418) to (358.0543, 46.4058)
  arc A9 centre (337.9421, 52.9821) radius 1.5 clockwise from (338.0324, 51.4848) to (337.9474, 54.4821)
  circle C8 centre (340.9421, 52.9717) radius 1.5
  arc A10 centre (337.9142, 44.9822) radius 1.5 clockwise from (337.909, 43.4822) to (337.92, 46.4822)
  circle C9 centre (340.9142, 44.9717) radius 1.5
  circle C10 centre (340.9421, 52.9717) radius 1.5
  arc A11 centre (363.942, 52.8914) radius 1.5 clockwise from (363.9457, 54.3914) to (363.9352, 51.3914)
  arc A12 centre (357.9141, 44.9124) radius 1.5 clockwise from (358.0439, 43.418) to (358.0543, 46.4058)
  arc A13 centre (357.942, 52.9123) radius 1.5 clockwise from (358.0718, 51.4179) to (358.0822, 54.4058)
  circle C11 centre (348.9491, 54.9437) radius 1.8
  circle C12 centre (360.942, 52.9018) radius 1.5
  arc A14 centre (343.9421, 52.9612) radius 1.5 clockwise from (343.9473, 54.4612) to (343.9361, 51.4612)
  circle C13 centre (360.9141, 44.9019) radius 1.5
  circle C14 centre (360.942, 52.9018) radius 1.5
  arc A15 centre (343.9142, 44.9612) radius 1.5 clockwise from (343.8396, 46.4594) to (343.909, 43.4612)
  arc A16 centre (357.942, 52.9123) radius 1.5 clockwise from (358.071, 51.4179) to (358.0816, 54.4058)
  arc A17 centre (357.942, 52.9123) radius 1.5 clockwise from (358.0718, 51.4179) to (358.0822, 54.4058)
  point P29 (390.4666, 44.9827)
  point P60 (390.4666, 44.9827)
  point P39 (390.4666, 52.9827)
  point P104 (390.4666, 52.9827)
  point P41 (390.4666, 44.9827)
  point P13 (387.4666, 52.9827)
  point P55 (387.4666, 52.9827)
  point P5 (387.4666, 44.9827)
  point P52 (387.4666, 44.9827)
  point P34 (384.4666, 52.9827)
  point P90 (384.4666, 52.9827)
  point P30 (384.4666, 44.9827)
  point P45 (384.4666, 44.9827)
  point P35 (344.3915, 62.0013)
  point P16 (343.3898, 37.963)
  point P22 (343.3898, 37.963)
  point P20 (343.3898, 37.963)
  point P108 (332.4666, 62.0013)
  point P125 (332.4666, 60.0013)
  coincident P29 P60
  coincident P39 P104
  perpendicular L10 L21
  perpendicular L11 L28
  coincident P29 P41
  perpendicular L4 L28
  coincident P13 P55
  coincident P5 P52
  coincident P34 P90
  coincident P30 P45
  coincident P35 L30
  perpendicular L6 L29
  coincident P16 P22
  perpendicular L3 L27
  perpendicular L9 L27
  coincident P16 P20
  perpendicular L3 L40
  perpendicular L22 L46
  dimension "d70" distance P108 P125 = 2
sketch "Sketch10" plane through (0, 0, 0) normal (0, 0, 1) x axis (1, 0, 0)
extrude "Extrude2" new body sketch "Bottom Runways" along normal blind 3 bodies "Left Loweer Deck Section"
extrude "Extrude3" add sketch "Bottom Runways" along normal blind 25
extrude "Extrude4" new body sketch "Bottom Runways" profile of L85 L50 L51 along normal blind 25 bodies "Middle Lower Deck Section"
extrude "Extrude5" add sketch "Bottom Runways" profile of L47 L85 along normal blind 25
extrude "Extrude6" add sketch "Bottom Runways" along normal blind 3
extrude "Extrude7" add sketch "Bottom Runways" along normal blind 25
extrude "Extrude8" new body sketch "Bottom Runways" along normal blind 3
extrude "Extrude9" new body sketch "Bottom Runways" along normal blind 25
extrude "Extrude10" add sketch "Bottom Runways" profile of L85 L58 L61 L62 L64 L65 L94 L92 along normal blind 3
extrude "Extrude11" add sketch "Bottom Runways" along normal blind 25
extrude "Extrude12" add sketch "Bottom Runways" profile of L85 L12 L19 L42 along normal blind 25
extrude "Extrude13" add sketch "Bottom Runways" along normal blind 25
extrude "Extrude15" add sketch "Bottom Runways" along normal blind 17
extrude "Extrude16" add sketch "Launch_reload_Plunger" profile of L1 C1 A1 C2 L3 L6 L7 L8 L9 L12 L14 L15 L18 A2 C3 A3 C4 A4 A5 A6 C5 C6 C7 A7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 along normal blind 8
extrude "Extrude17" cut sketch "Launch_reload_Plunger" profile of C1 A1 C2 L3 L6 L8 L14 A2 C3 A3 C4 A4 A5 A6 C5 C6 C7 A7 A8 A9 C8 A10 C9 C10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 along normal blind 10
extrude "Extrude18" cut sketch "Bottom Runways" along normal blind 4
